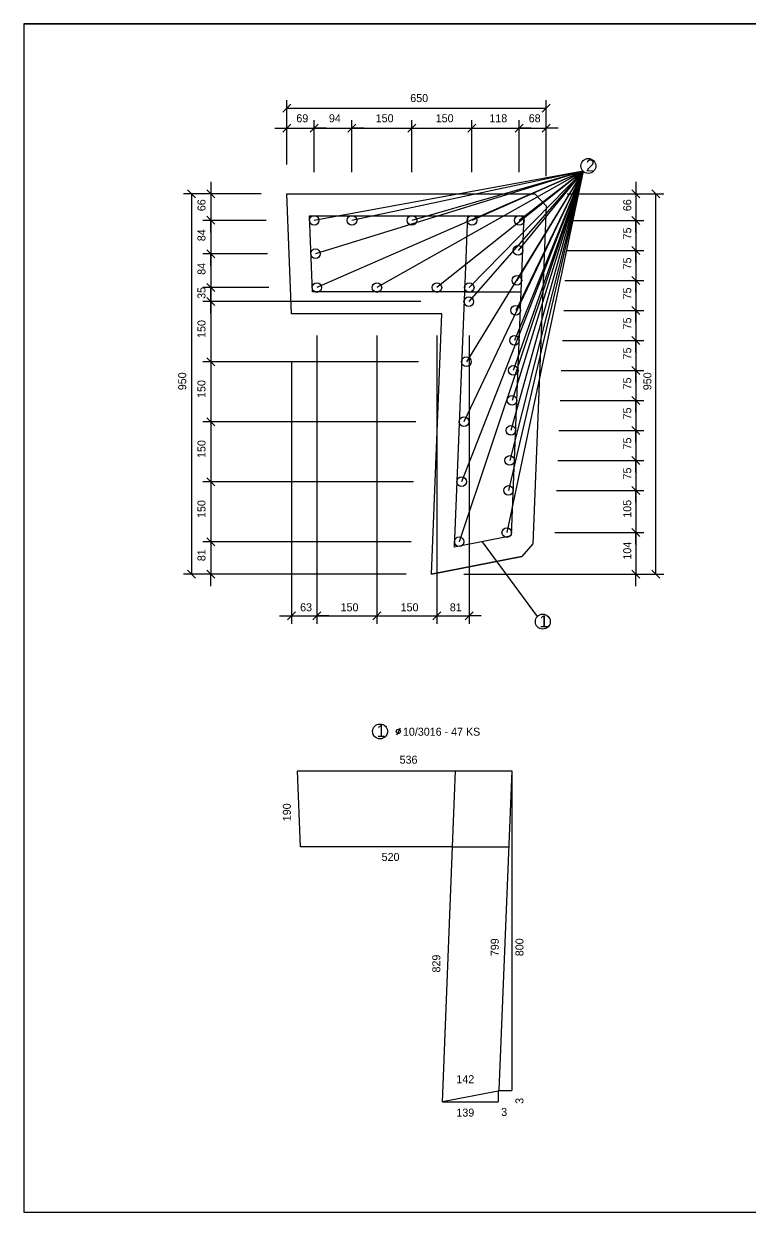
# Model space of a CAD drawing. Extents: x -577057.43 to -577053.23, y -1159996.61 to -1159993.64.
# Drawn here: x -577057.434 to -577055.626, y -1159996.607 to -1159993.637 of the extents above; entities that cross this region are included whole.
import ezdxf

# ---------------------------------------------------------------- set-up
doc = ezdxf.new("R2010")
doc.units = 0
doc.layers.add('_římsa', color=7, linetype='Continuous')

msp = doc.modelspace()

# ---------------------------------------------------------------- linework, layer by layer
for p, q in [((-577053.2338, -1159993.6371), (-577057.4338, -1159993.6371)), ((-577057.4338, -1159993.6371), (-577057.4338, -1159996.6071)), ((-577056.7667, -1159993.8378), (-577056.7867, -1159993.8578)), ((-577056.7767, -1159993.9887), (-577056.7767, -1159993.8278)), ((-577056.7767, -1159993.8478), (-577056.1279, -1159993.8478)), ((-577056.1179, -1159993.8378), (-577056.1379, -1159993.8578)), ((-577056.1279, -1159994.0182), (-577056.1279, -1159993.8278)), ((-577056.7767, -1159993.9423), (-577056.7767, -1159993.8782)), ((-577056.708, -1159994.0083), (-577056.708, -1159993.8782)), ((-577056.6137, -1159994.0083), (-577056.6137, -1159993.8782)), ((-577056.4637, -1159994.0083), (-577056.4637, -1159993.8782)), ((-577056.3137, -1159994.0083), (-577056.3137, -1159993.8782)), ((-577056.1954, -1159994.0083), (-577056.1954, -1159993.8782)), ((-577056.1279, -1159993.9718), (-577056.1279, -1159993.8782)), ((-577056.8067, -1159993.8982), (-577056.7767, -1159993.8982)), ((-577056.7667, -1159993.8882), (-577056.7867, -1159993.9082)), ((-577056.7767, -1159993.8982), (-577056.708, -1159993.8982)), ((-577056.738, -1159993.8982), (-577056.708, -1159993.8982)), ((-577056.698, -1159993.8882), (-577056.718, -1159993.9082)), ((-577056.678, -1159993.8982), (-577056.708, -1159993.8982)), ((-577056.708, -1159993.8982), (-577056.6137, -1159993.8982)), ((-577056.6037, -1159993.8882), (-577056.6237, -1159993.9082)), ((-577056.5837, -1159993.8982), (-577056.6137, -1159993.8982)), ((-577056.6137, -1159993.8982), (-577056.4637, -1159993.8982)), ((-577056.4537, -1159993.8882), (-577056.4737, -1159993.9082)), ((-577056.4637, -1159993.8982), (-577056.3137, -1159993.8982)), ((-577056.3437, -1159993.8982), (-577056.3137, -1159993.8982)), ((-577056.3037, -1159993.8882), (-577056.3237, -1159993.9082)), ((-577056.3137, -1159993.8982), (-577056.1954, -1159993.8982)), ((-577056.2254, -1159993.8982), (-577056.1954, -1159993.8982)), ((-577056.1854, -1159993.8882), (-577056.2054, -1159993.9082)), ((-577056.1654, -1159993.8982), (-577056.1954, -1159993.8982)), ((-577056.1954, -1159993.8982), (-577056.1279, -1159993.8982)), ((-577056.1179, -1159993.8882), (-577056.1379, -1159993.9082)), ((-577056.0979, -1159993.8982), (-577056.1279, -1159993.8982)), ((-577056.0359, -1159994.0054), (-577056.708, -1159994.1283)), ((-577056.0359, -1159994.0054), (-577056.7047, -1159994.2118)), ((-577056.0359, -1159994.0054), (-577056.7013, -1159994.2963)), ((-577056.0359, -1159994.0054), (-577056.6137, -1159994.1283)), ((-577056.0359, -1159994.0054), (-577056.5513, -1159994.2963)), ((-577056.0359, -1159994.0054), (-577056.4637, -1159994.1283)), ((-577056.0359, -1159994.0054), (-577056.4013, -1159994.2963)), ((-577056.0359, -1159994.0054), (-577056.3456, -1159994.9315)), ((-577056.0359, -1159994.0054), (-577056.3396, -1159994.7815)), ((-577056.0359, -1159994.0054), (-577056.3336, -1159994.6315)), ((-577056.0359, -1159994.0054), (-577056.3276, -1159994.4815)), ((-577056.0359, -1159994.0054), (-577056.3216, -1159994.3315)), ((-577056.0359, -1159994.0054), (-577056.3205, -1159994.2963)), ((-577056.0359, -1159994.0054), (-577056.3137, -1159994.1283)), ((-577056.0359, -1159994.0054), (-577056.2266, -1159994.9085)), ((-577056.0359, -1159994.0054), (-577056.2224, -1159994.8033)), ((-577056.0359, -1159994.0054), (-577056.2194, -1159994.7283)), ((-577056.0359, -1159994.0054), (-577056.2164, -1159994.6533)), ((-577056.0359, -1159994.0054), (-577056.2134, -1159994.5783)), ((-577056.0359, -1159994.0054), (-577056.2104, -1159994.5033)), ((-577056.0359, -1159994.0054), (-577056.2074, -1159994.4283)), ((-577056.0359, -1159994.0054), (-577056.2044, -1159994.3533)), ((-577056.0359, -1159994.0054), (-577056.2014, -1159994.2783)), ((-577056.0359, -1159994.0054), (-577056.1984, -1159994.2033)), ((-577056.0359, -1159994.0054), (-577056.1954, -1159994.1283)), ((-577057.0048, -1159994.0723), (-577057.0248, -1159994.0523)), ((-577056.9567, -1159994.0723), (-577056.9767, -1159994.0523)), ((-577056.9667, -1159994.0323), (-577056.9667, -1159994.0623)), ((-577055.8943, -1159994.0723), (-577055.9143, -1159994.0523)), ((-577055.9043, -1159994.0323), (-577055.9043, -1159994.0623)), ((-577055.844, -1159994.0723), (-577055.864, -1159994.0523)), ((-577056.8402, -1159994.0623), (-577057.0348, -1159994.0623)), ((-577057.0148, -1159994.0623), (-577057.0148, -1159995.0123)), ((-577056.8967, -1159994.0623), (-577056.9867, -1159994.0623)), ((-577056.9667, -1159994.0623), (-577056.9667, -1159994.1283)), ((-577056.0756, -1159994.0623), (-577055.834, -1159994.0623)), ((-577056.0363, -1159994.0623), (-577055.8843, -1159994.0623)), ((-577055.9043, -1159994.0623), (-577055.9043, -1159994.1283)), ((-577055.854, -1159995.0123), (-577055.854, -1159994.0623)), ((-577056.9667, -1159994.0983), (-577056.9667, -1159994.1283)), ((-577056.3317, -1159994.3073), (-577056.3241, -1159994.1173)), ((-577055.9043, -1159994.0983), (-577055.9043, -1159994.1283)), ((-577056.828, -1159994.1283), (-577056.9867, -1159994.1283)), ((-577056.9567, -1159994.138), (-577056.9767, -1159994.118)), ((-577056.9667, -1159994.1583), (-577056.9667, -1159994.1283)), ((-577056.9667, -1159994.1283), (-577056.9667, -1159994.2118)), ((-577056.0754, -1159994.1283), (-577055.8843, -1159994.1283)), ((-577055.8943, -1159994.1383), (-577055.9143, -1159994.1183)), ((-577055.9043, -1159994.1583), (-577055.9043, -1159994.1283)), ((-577055.9043, -1159994.1283), (-577055.9043, -1159994.2033)), ((-577055.9043, -1159994.1733), (-577055.9043, -1159994.2033)), ((-577056.9567, -1159994.2218), (-577056.9767, -1159994.2018)), ((-577056.9667, -1159994.1818), (-577056.9667, -1159994.2118)), ((-577056.0784, -1159994.2033), (-577055.8843, -1159994.2033)), ((-577055.8943, -1159994.2133), (-577055.9143, -1159994.1933)), ((-577055.9043, -1159994.2333), (-577055.9043, -1159994.2033)), ((-577055.9043, -1159994.2033), (-577055.9043, -1159994.2783)), ((-577056.8247, -1159994.2118), (-577056.9867, -1159994.2118)), ((-577056.9667, -1159994.2418), (-577056.9667, -1159994.2118)), ((-577056.9667, -1159994.2118), (-577056.9667, -1159994.2963)), ((-577055.9043, -1159994.2483), (-577055.9043, -1159994.2783)), ((-577056.9567, -1159994.3063), (-577056.9767, -1159994.2863)), ((-577056.9667, -1159994.2663), (-577056.9667, -1159994.2963)), ((-577056.0814, -1159994.2783), (-577055.8843, -1159994.2783)), ((-577055.8943, -1159994.2883), (-577055.9143, -1159994.2683)), ((-577055.9043, -1159994.3083), (-577055.9043, -1159994.2783)), ((-577055.9043, -1159994.2783), (-577055.9043, -1159994.3533)), ((-577056.8213, -1159994.2963), (-577056.9867, -1159994.2963)), ((-577056.9567, -1159994.3415), (-577056.9767, -1159994.3215)), ((-577056.9667, -1159994.3263), (-577056.9667, -1159994.2963)), ((-577056.9667, -1159994.2963), (-577056.9667, -1159994.3315)), ((-577056.3317, -1159994.3073), (-577056.1916, -1159994.3073)), ((-577055.9043, -1159994.3233), (-577055.9043, -1159994.3533)), ((-577056.4416, -1159994.3315), (-577056.9867, -1159994.3315)), ((-577056.9667, -1159994.3615), (-577056.9667, -1159994.3315)), ((-577056.9667, -1159994.3315), (-577056.9667, -1159994.4815)), ((-577056.0844, -1159994.3533), (-577055.8843, -1159994.3533)), ((-577055.8943, -1159994.3633), (-577055.9143, -1159994.3433)), ((-577055.9043, -1159994.3833), (-577055.9043, -1159994.3533)), ((-577055.9043, -1159994.3533), (-577055.9043, -1159994.4283)), ((-577056.3889, -1159994.3623), (-577056.7647, -1159994.3623)), ((-577056.4149, -1159995.0123), (-577056.3889, -1159994.3623)), ((-577055.9043, -1159994.3983), (-577055.9043, -1159994.4283)), ((-577056.7013, -1159994.4163), (-577056.7013, -1159995.137)), ((-577056.5513, -1159994.4163), (-577056.5513, -1159995.137)), ((-577056.4013, -1159994.4163), (-577056.4013, -1159995.137)), ((-577056.3205, -1159994.4163), (-577056.3205, -1159995.137)), ((-577056.0874, -1159994.4283), (-577055.8843, -1159994.4283)), ((-577055.8943, -1159994.4383), (-577055.9143, -1159994.4183)), ((-577055.9043, -1159994.4583), (-577055.9043, -1159994.4283)), ((-577055.9043, -1159994.4283), (-577055.9043, -1159994.5033)), ((-577056.9567, -1159994.4915), (-577056.9767, -1159994.4715)), ((-577055.9043, -1159994.4733), (-577055.9043, -1159994.5033)), ((-577056.4476, -1159994.4815), (-577056.9867, -1159994.4815)), ((-577056.9667, -1159994.4815), (-577056.9667, -1159994.6315)), ((-577056.7647, -1159994.4823), (-577056.7647, -1159995.137)), ((-577056.0904, -1159994.5033), (-577055.8843, -1159994.5033)), ((-577055.8943, -1159994.5133), (-577055.9143, -1159994.4933)), ((-577055.9043, -1159994.5333), (-577055.9043, -1159994.5033)), ((-577055.9043, -1159994.5033), (-577055.9043, -1159994.5783)), ((-577055.9043, -1159994.5483), (-577055.9043, -1159994.5783)), ((-577056.0934, -1159994.5783), (-577055.8843, -1159994.5783)), ((-577055.8943, -1159994.5883), (-577055.9143, -1159994.5683)), ((-577055.9043, -1159994.6083), (-577055.9043, -1159994.5783)), ((-577055.9043, -1159994.5783), (-577055.9043, -1159994.6533)), ((-577056.9567, -1159994.6415), (-577056.9767, -1159994.6215)), ((-577056.4536, -1159994.6315), (-577056.9867, -1159994.6315)), ((-577056.9667, -1159994.6315), (-577056.9667, -1159994.7815)), ((-577055.8943, -1159994.6633), (-577055.9143, -1159994.6433)), ((-577055.9043, -1159994.6233), (-577055.9043, -1159994.6533)), ((-577056.0964, -1159994.6533), (-577055.8843, -1159994.6533)), ((-577055.9043, -1159994.6833), (-577055.9043, -1159994.6533)), ((-577055.9043, -1159994.6533), (-577055.9043, -1159994.7283)), ((-577055.9043, -1159994.6983), (-577055.9043, -1159994.7283)), ((-577056.0994, -1159994.7283), (-577055.8843, -1159994.7283)), ((-577055.8943, -1159994.7383), (-577055.9143, -1159994.7183)), ((-577055.9043, -1159994.7583), (-577055.9043, -1159994.7283)), ((-577055.9043, -1159994.7283), (-577055.9043, -1159994.8033)), ((-577056.4596, -1159994.7815), (-577056.9867, -1159994.7815)), ((-577056.9567, -1159994.7915), (-577056.9767, -1159994.7715)), ((-577056.9667, -1159994.7815), (-577056.9667, -1159994.9315)), ((-577055.8943, -1159994.8133), (-577055.9143, -1159994.7933)), ((-577055.9043, -1159994.7733), (-577055.9043, -1159994.8033)), ((-577056.1024, -1159994.8033), (-577055.8843, -1159994.8033)), ((-577055.9043, -1159994.8333), (-577055.9043, -1159994.8033)), ((-577055.9043, -1159994.8033), (-577055.9043, -1159994.9085)), ((-577055.9043, -1159994.8785), (-577055.9043, -1159994.9085)), ((-577056.9667, -1159994.9015), (-577056.9667, -1159994.9315)), ((-577056.1066, -1159994.9085), (-577055.8843, -1159994.9085)), ((-577055.8943, -1159994.9185), (-577055.9143, -1159994.8985)), ((-577055.9043, -1159994.9385), (-577055.9043, -1159994.9085)), ((-577055.9043, -1159994.9085), (-577055.9043, -1159995.0123)), ((-577056.4656, -1159994.9315), (-577056.9867, -1159994.9315)), ((-577056.9567, -1159994.9415), (-577056.9767, -1159994.9215)), ((-577056.9667, -1159994.9315), (-577056.9667, -1159995.0123)), ((-577056.1498, -1159995.118), (-577056.2876, -1159994.9314)), ((-577056.4149, -1159995.0123), (-577056.1887, -1159994.9681)), ((-577057.0048, -1159995.0223), (-577057.0248, -1159995.0023)), ((-577056.9567, -1159995.0223), (-577056.9767, -1159995.0023)), ((-577055.8943, -1159995.0223), (-577055.9143, -1159995.0023)), ((-577055.844, -1159995.0223), (-577055.864, -1159995.0023)), ((-577056.4784, -1159995.0123), (-577057.0348, -1159995.0123)), ((-577056.5349, -1159995.0123), (-577056.9867, -1159995.0123)), ((-577056.9667, -1159995.0423), (-577056.9667, -1159995.0123)), ((-577056.3342, -1159995.0123), (-577055.834, -1159995.0123)), ((-577056.2949, -1159995.0123), (-577055.8843, -1159995.0123)), ((-577055.9043, -1159995.0423), (-577055.9043, -1159995.0123)), ((-577056.7947, -1159995.117), (-577056.7647, -1159995.117)), ((-577056.7547, -1159995.107), (-577056.7747, -1159995.127)), ((-577056.7647, -1159995.117), (-577056.7013, -1159995.117)), ((-577056.6913, -1159995.107), (-577056.7113, -1159995.127)), ((-577056.6713, -1159995.117), (-577056.7013, -1159995.117)), ((-577056.7013, -1159995.117), (-577056.5513, -1159995.117)), ((-577056.5413, -1159995.107), (-577056.5613, -1159995.127)), ((-577056.5513, -1159995.117), (-577056.4013, -1159995.117)), ((-577056.4313, -1159995.117), (-577056.4013, -1159995.117)), ((-577056.3913, -1159995.107), (-577056.4113, -1159995.127)), ((-577056.4013, -1159995.117), (-577056.3205, -1159995.117)), ((-577056.3105, -1159995.107), (-577056.3305, -1159995.127)), ((-577056.2905, -1159995.117), (-577056.3205, -1159995.117)), ((-577056.362, -1159995.6938), (-577056.3544, -1159995.5038)), ((-577056.2143, -1159995.5038), (-577056.2143, -1159996.3031)), ((-577056.362, -1159995.6938), (-577056.2219, -1159995.6938)), ((-577056.2484, -1159996.3044), (-577056.2484, -1159996.3315)), ((-577056.2473, -1159996.3031), (-577056.2143, -1159996.3031)), ((-577056.3876, -1159996.3315), (-577056.2484, -1159996.3315)), ((-577057.4338, -1159996.6071), (-577053.2338, -1159996.6071))]:
    msp.add_line(p, q)
for points in [[(-577057.4338, -1159993.6371), (-577053.2338, -1159993.6371)], [(-577056.7647, -1159994.3623), (-577056.7767, -1159994.0623), (-577056.1563, -1159994.0623)], [(-577056.1563, -1159994.0623), (-577056.1279, -1159994.0918), (-577056.1617, -1159994.9366)], [(-577056.1617, -1159994.9366), (-577056.1887, -1159994.9681), (-577056.4149, -1159995.0123)]]:
    msp.add_lwpolyline(points)
for points in [[(-577056.7119, -1159994.3073), (-577056.7195, -1159994.1173), (-577056.184, -1159994.1173), (-577056.2159, -1159994.9153), (-577056.218, -1159994.9178), (-577056.3572, -1159994.945), (-577056.3317, -1159994.3073)], [(-577056.7422, -1159995.6938), (-577056.7498, -1159995.5038), (-577056.2143, -1159995.5038), (-577056.2463, -1159996.3019), (-577056.2484, -1159996.3044), (-577056.3876, -1159996.3315), (-577056.362, -1159995.6938)]]:
    msp.add_lwpolyline(points, close=True)
for centre in [(-577056.708, -1159994.1283), (-577056.6137, -1159994.1283), (-577056.4637, -1159994.1283), (-577056.3137, -1159994.1283), (-577056.1954, -1159994.1283), (-577056.7047, -1159994.2118), (-577056.1984, -1159994.2033), (-577056.7013, -1159994.2963), (-577056.5513, -1159994.2963), (-577056.4013, -1159994.2963), (-577056.3205, -1159994.2963), (-577056.2014, -1159994.2783), (-577056.3216, -1159994.3315), (-577056.2044, -1159994.3533), (-577056.2074, -1159994.4283), (-577056.3276, -1159994.4815), (-577056.2104, -1159994.5033), (-577056.2134, -1159994.5783), (-577056.3336, -1159994.6315), (-577056.2164, -1159994.6533), (-577056.2194, -1159994.7283), (-577056.3396, -1159994.7815), (-577056.2224, -1159994.8033), (-577056.2266, -1159994.9085), (-577056.3456, -1159994.9315)]:
    msp.add_circle(centre, 0.012)
at = {"layer": '_římsa'}
msp.add_line((-577056.4933, -1159995.3973), (-577056.5026, -1159995.4152), dxfattribs=at)
for centre, radius in [((-577056.0227, -1159993.9923), 0.0186), ((-577056.1366, -1159995.1311), 0.0186), ((-577056.5433, -1159995.4056), 0.0186), ((-577056.4976, -1159995.4055), 0.00525)]:
    msp.add_circle(centre, radius, dxfattribs=at)

# ---------------------------------------------------------------- texts
for s, p in [('650', (-577056.4679, -1159993.8328)), ('69', (-577056.7525, -1159993.8832)), ('94', (-577056.6712, -1159993.8832)), ('150', (-577056.5542, -1159993.8832)), ('150', (-577056.4042, -1159993.8832)), ('118', (-577056.2701, -1159993.8832)), ('68', (-577056.1718, -1159993.8832)), ('63', (-577056.7431, -1159995.1053)), ('150', (-577056.6419, -1159995.1053)), ('150', (-577056.4919, -1159995.1053)), ('81', (-577056.369, -1159995.1053))]:
    msp.add_text(s, height=0.02).set_placement(p)
for s, p in [('66', (-577056.9797, -1159994.1054)), ('66', (-577055.9156, -1159994.1054)), ('75', (-577055.9156, -1159994.1759)), ('84', (-577056.9797, -1159994.1804)), ('84', (-577056.9797, -1159994.2644)), ('75', (-577055.9156, -1159994.2509)), ('35', (-577056.9797, -1159994.3246)), ('75', (-577055.9156, -1159994.3259)), ('150', (-577056.9797, -1159994.4221)), ('75', (-577055.9156, -1159994.4009)), ('75', (-577055.9156, -1159994.4759)), ('950', (-577057.0278, -1159994.5528)), ('150', (-577056.9797, -1159994.5721)), ('75', (-577055.9156, -1159994.5509)), ('950', (-577055.8653, -1159994.5528)), ('75', (-577055.9156, -1159994.6259)), ('150', (-577056.9797, -1159994.7221)), ('75', (-577055.9156, -1159994.7009)), ('75', (-577055.9156, -1159994.7759)), ('150', (-577056.9797, -1159994.8721)), ('105', (-577055.9156, -1159994.8715)), ('104', (-577055.9156, -1159994.9762)), ('81', (-577056.9797, -1159994.98))]:
    msp.add_text(s, height=0.02, rotation=90).set_placement(p)
for s, height, rotation, p in [('2', 0.03, 360, (-577056.0291, -1159994.0062)), ('1', 0.03, 360, (-577056.1451, -1159995.1451)), ('1', 0.03, 360, (-577056.5519, -1159995.4195)), ('536', 0.02, 0, (-577056.4945, -1159995.4861)), ('190', 0.02, 90, (-577056.7664, -1159995.6299)), ('520', 0.02, 0, (-577056.5394, -1159995.7292)), ('799', 0.02, 90, (-577056.2467, -1159995.9672)), ('800', 0.02, 90, (-577056.185, -1159995.9672)), ('829', 0.02, 90, (-577056.3928, -1159996.008)), ('142', 0.02, 0.0011, (-577056.3526, -1159996.2846)), ('3', 0.02, 90, (-577056.185, -1159996.3364)), ('139', 0.02, 0.0011, (-577056.3526, -1159996.3681)), ('3', 0.02, 0.0011, (-577056.2407, -1159996.3664))]:
    msp.add_text(s, height=height, rotation=rotation, dxfattribs=at).set_placement(p)
msp.add_text('10/3016 - 47 KS', height=0.02, dxfattribs=at).set_placement((-577056.4862, -1159995.4163))

doc.saveas('drawing.dxf')
